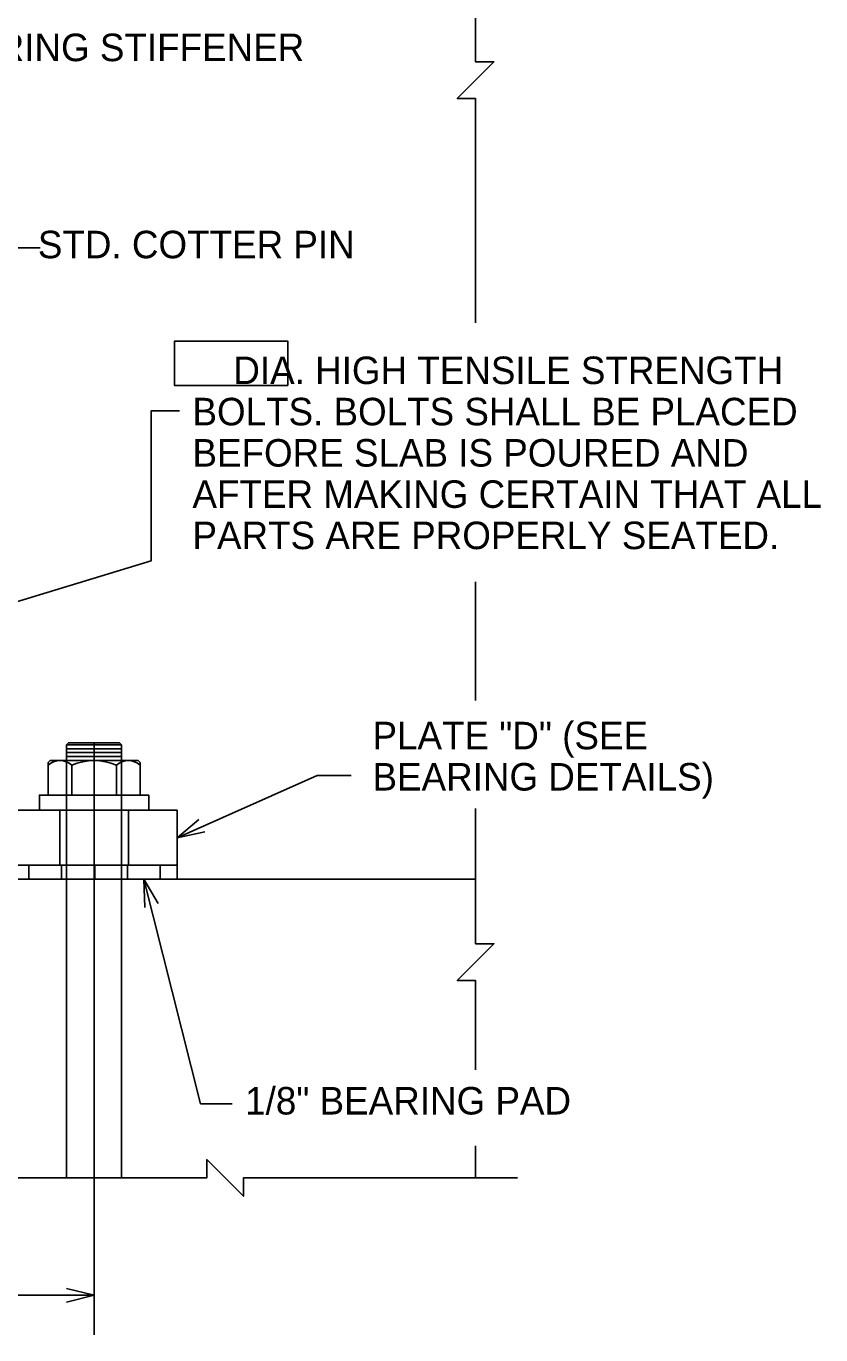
# Model space of a CAD drawing. Extents: x -1.5 to 34.7, y 2.5 to 26.9.
# Drawn here: x 16.34 to 19.95, y 16.09 to 22.04 of the extents above; entities that cross this region are included whole.
import ezdxf

# ---------------------------------------------------------------- set-up
doc = ezdxf.new("R2010")
doc.units = 0
doc.layers.add('Level 2', color=7, linetype='Continuous')

msp = doc.modelspace()

# ---------------------------------------------------------------- linework, layer by layer
at = {"layer": 'Level 2'}
for p, q in [((16.3998, 21.0308), (16.1655, 21.0308)), ((16.9035, 19.6085), (16.1949, 19.393)), ((16.5282, 18.782), (16.5192, 18.773)), ((16.5192, 18.7028), (16.5192, 18.773)), ((16.7692, 18.773), (16.5192, 18.773)), ((16.7692, 18.755), (16.5192, 18.755)), ((16.7692, 18.737), (16.5192, 18.737)), ((16.5282, 18.782), (16.7602, 18.782)), ((16.6442, 16.272), (16.6442, 18.782)), ((16.7692, 18.773), (16.7602, 18.782)), ((16.7692, 18.773), (16.7692, 18.7028)), ((16.444, 18.7008), (16.435, 18.6918)), ((16.435, 18.544), (16.435, 18.6918)), ((16.444, 18.7008), (16.8445, 18.7008)), ((16.7692, 18.719), (16.5192, 18.719)), ((16.5192, 18.7008), (16.5192, 18.4753)), ((16.543, 18.544), (16.543, 18.6799)), ((16.7455, 18.6799), (16.7455, 18.544)), ((16.7692, 18.7008), (16.7692, 18.4753)), ((16.8445, 18.7008), (16.8535, 18.6918)), ((16.8535, 18.6918), (16.8535, 18.544)), ((17.6575, 18.6327), (17.0217, 18.3503)), ((17.8128, 18.6327), (17.6575, 18.6327)), ((17.0217, 18.4753), (11.7924, 18.4753)), ((16.4879, 18.2253), (16.4879, 18.4753)), ((16.5192, 18.4753), (16.5192, 16.805)), ((16.7692, 18.4753), (16.7692, 16.805)), ((16.8005, 18.2253), (16.8005, 18.4753)), ((17.0217, 18.1626), (17.0217, 18.4753)), ((17.0217, 18.3503), (17.1203, 18.4332)), ((17.0217, 18.3503), (17.1477, 18.377)), ((17.0217, 18.2253), (11.7924, 18.2253)), ((17.0217, 18.2253), (17.0217, 18.1626)), ((9.9734, 18.1626), (18.3775, 18.1626)), ((17.1277, 17.1413), (16.8704, 18.1626)), ((16.8704, 18.1626), (16.9349, 18.051)), ((16.8704, 18.1626), (16.8748, 18.0338)), ((17.2711, 17.1413), (17.1277, 17.1413)), ((16.6442, 16.4519), (16.6442, 16.272)), ((16.6442, 16.272), (16.5192, 16.3032)), ((12.1684, 16.272), (16.6442, 16.272)), ((16.6442, 16.272), (16.5192, 16.2407)), ((16.6442, 16.272), (16.6442, 16.092))]:
    msp.add_line(p, q, dxfattribs=at)
for points in [[(18.3775, 20.6903), (18.3775, 21.709), (18.2942, 21.709), (18.4609, 21.8757), (18.3775, 21.8757), (18.3775, 22.5464)], [(16.9035, 19.6085), (16.9035, 20.2897), (17.0318, 20.2897)], [(18.3775, 18.9733), (18.3775, 19.5132)], [(18.3775, 17.2966), (18.3775, 17.7018), (18.2942, 17.7018), (18.4609, 17.8685), (18.3775, 17.8685), (18.3775, 18.4833)], [(18.3775, 16.805), (18.3775, 16.9501)], [(16.2448, 16.805), (17.1557, 16.805), (17.1557, 16.8884), (17.3224, 16.7217), (17.3224, 16.805), (18.5686, 16.805)]]:
    msp.add_lwpolyline(points, dxfattribs=at)
for points in [[(17.5245, 20.4057), (17.5245, 20.6059), (17.0092, 20.6059), (17.0092, 20.4057)], [(16.8928, 18.544), (16.3956, 18.544), (16.3956, 18.4753), (16.8928, 18.4753)], [(16.3477, 18.2253), (16.4958, 18.2253), (16.4958, 18.1626), (16.3477, 18.1626)], [(16.6472, 18.2253), (16.7953, 18.2253), (16.7953, 18.1626), (16.6472, 18.1626)], [(16.9444, 18.2253), (17.0217, 18.2253), (17.0217, 18.1626), (16.9444, 18.1626)]]:
    msp.add_lwpolyline(points, close=True, dxfattribs=at)
for centre, radius, start, end in [((16.489, 18.6206), 0.0802, 47.64442, 132.35558), ((16.6442, 18.4453), 0.2555, 66.65071, 113.34929), ((16.7995, 18.6206), 0.0802, 47.64442, 132.35558)]:
    msp.add_arc(centre, radius, start, end, dxfattribs=at)

# ---------------------------------------------------------------- texts
for s, p in [('BEARING STIFFENER', (15.8717, 21.8788)), (' STD. COTTER PIN', (16.3424, 20.9833)), ('    DIA. HIGH TENSILE STRENGTH', (17.0911, 20.4117)), ('BOLTS. BOLTS SHALL BE PLACED', (17.0911, 20.2242)), ('BEFORE SLAB IS POURED AND', (17.0911, 20.0367)), ('AFTER MAKING CERTAIN THAT ALL', (17.0911, 19.8492)), ('PARTS ARE PROPERLY SEATED.', (17.0911, 19.6617)), ('PLATE "D" (SEE ', (17.9091, 18.7524)), ('BEARING DETAILS)', (17.9091, 18.5649)), ('1/8" BEARING PAD', (17.3306, 17.093))]:
    msp.add_text(s, height=0.125, dxfattribs=at).set_placement(p)

doc.saveas('drawing.dxf')
